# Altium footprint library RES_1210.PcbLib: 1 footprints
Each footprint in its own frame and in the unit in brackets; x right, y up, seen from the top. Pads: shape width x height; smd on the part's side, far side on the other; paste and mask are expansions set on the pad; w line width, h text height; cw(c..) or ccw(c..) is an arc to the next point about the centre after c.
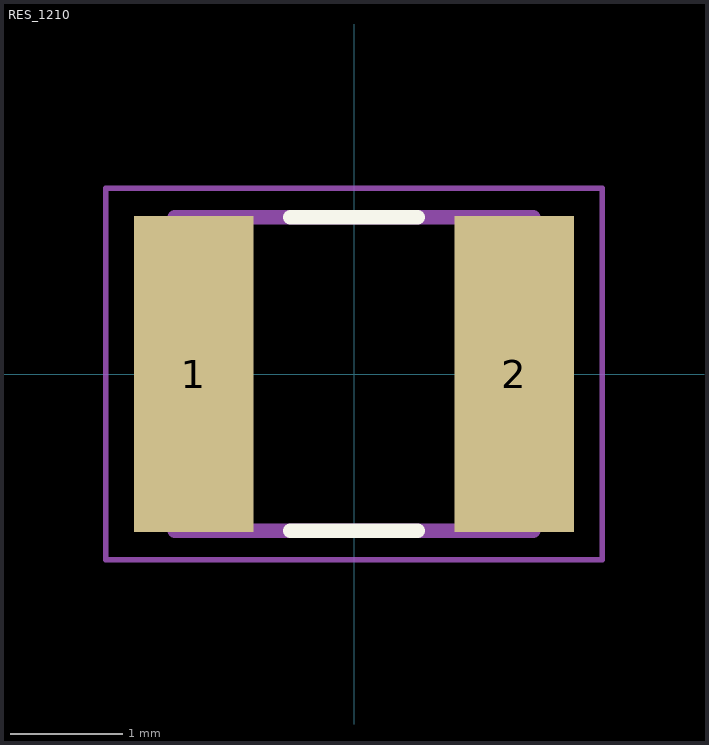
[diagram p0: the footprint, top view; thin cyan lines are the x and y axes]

## RES_1210 [mm]
pads (2):
  rect 1.07x2.82 smd: 1(-1.43,0) 2(1.43,0)
Top Overlay:
  lines w0.127: -0.57,-1.4 0.57,-1.4 ; -0.57,1.4 0.57,1.4
Mechanical 13:
  lines w0.127: -1.6,-1.4 1.6,-1.4 1.6,1.4 -1.6,1.4 -1.6,-1.4
Mechanical 15:
  lines w0.05: -2.215,-1.658 2.215,-1.658 2.215,1.658 -2.215,1.658 -2.215,-1.658
3D body "RES_1210.STEP": height 0.65, standoff 0, extent -1.55,-1.3 1.55,1.3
